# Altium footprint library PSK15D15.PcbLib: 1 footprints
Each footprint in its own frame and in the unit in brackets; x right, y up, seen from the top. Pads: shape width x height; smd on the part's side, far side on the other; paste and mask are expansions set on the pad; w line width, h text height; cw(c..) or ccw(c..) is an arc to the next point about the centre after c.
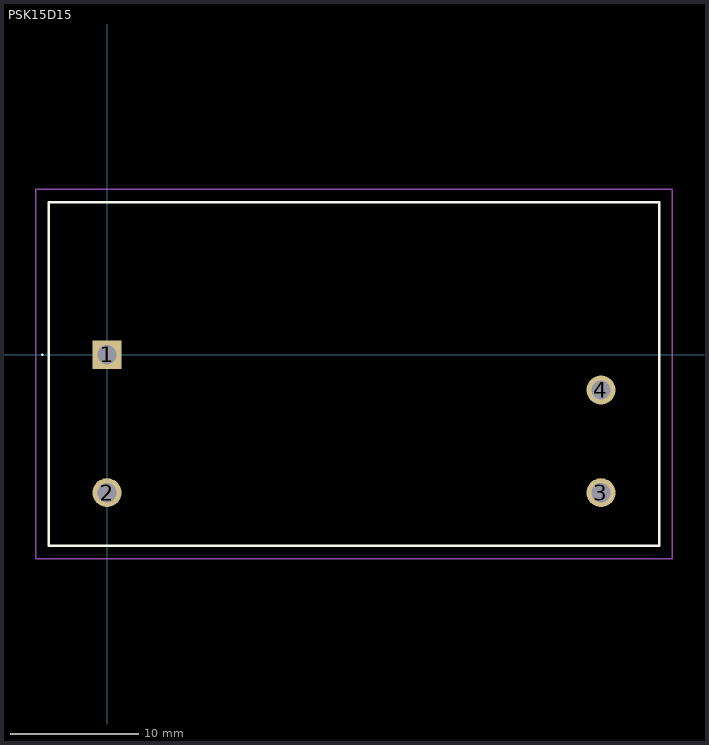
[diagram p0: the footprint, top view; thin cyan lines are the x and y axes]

## PSK15D15 [mm]
pads (4):
  rect 2.25x2.25 hole 1.5: 1(0,0)
  round 2.25 hole 1.5: 2(0,-10.75) 3(38.5,-10.75) 4(38.5,-2.75)
Top Overlay:
  lines w0.1: -5.1,0 -5.1,0 ; -5.1,0 ccw(c-5.05,0) -5,0 ; -5.1,0 cw(c-5.05,0) -5,0 ; -5,0 -5,0
  lines w0.2: -4.55,-14.9 43.05,-14.9 43.05,11.9 -4.55,11.9 -4.55,-14.9
Mechanical 15:
  lines w0.1: -4.55,-14.9 43.05,-14.9 43.05,11.9 -4.55,11.9 -4.55,-14.9
Mechanical 20:
  lines w0.1: -5.55,-15.9 44.05,-15.9 44.05,12.9 -5.55,12.9 -5.55,-15.9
